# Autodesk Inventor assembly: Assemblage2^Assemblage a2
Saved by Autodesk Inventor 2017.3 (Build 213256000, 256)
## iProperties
Created: 2011-01
Part Number: Assemblage2^Assemblage a2
Material: Générique
Document SubType Name: Assembly
Designer: ficho
Author: ficho
Sending System: SolidWorks 2009
Last Author: christophe
Last Saved: 2011-02-10
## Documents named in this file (1)
- G:\travail\année 2019-2020\réforme\toussaint\Serrure biométrique SET\Documentations_pedagogique\Modelisation_Solidworks\Assemblage2^Assemblage a2.iam
